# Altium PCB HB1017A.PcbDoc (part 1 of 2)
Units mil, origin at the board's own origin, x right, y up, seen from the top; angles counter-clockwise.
Board outline 2906.96 x 3469.35 mil, 2 copper layers (Top Layer, Bottom Layer); 52 components, 64 nets, 277 pads, 519 vias.
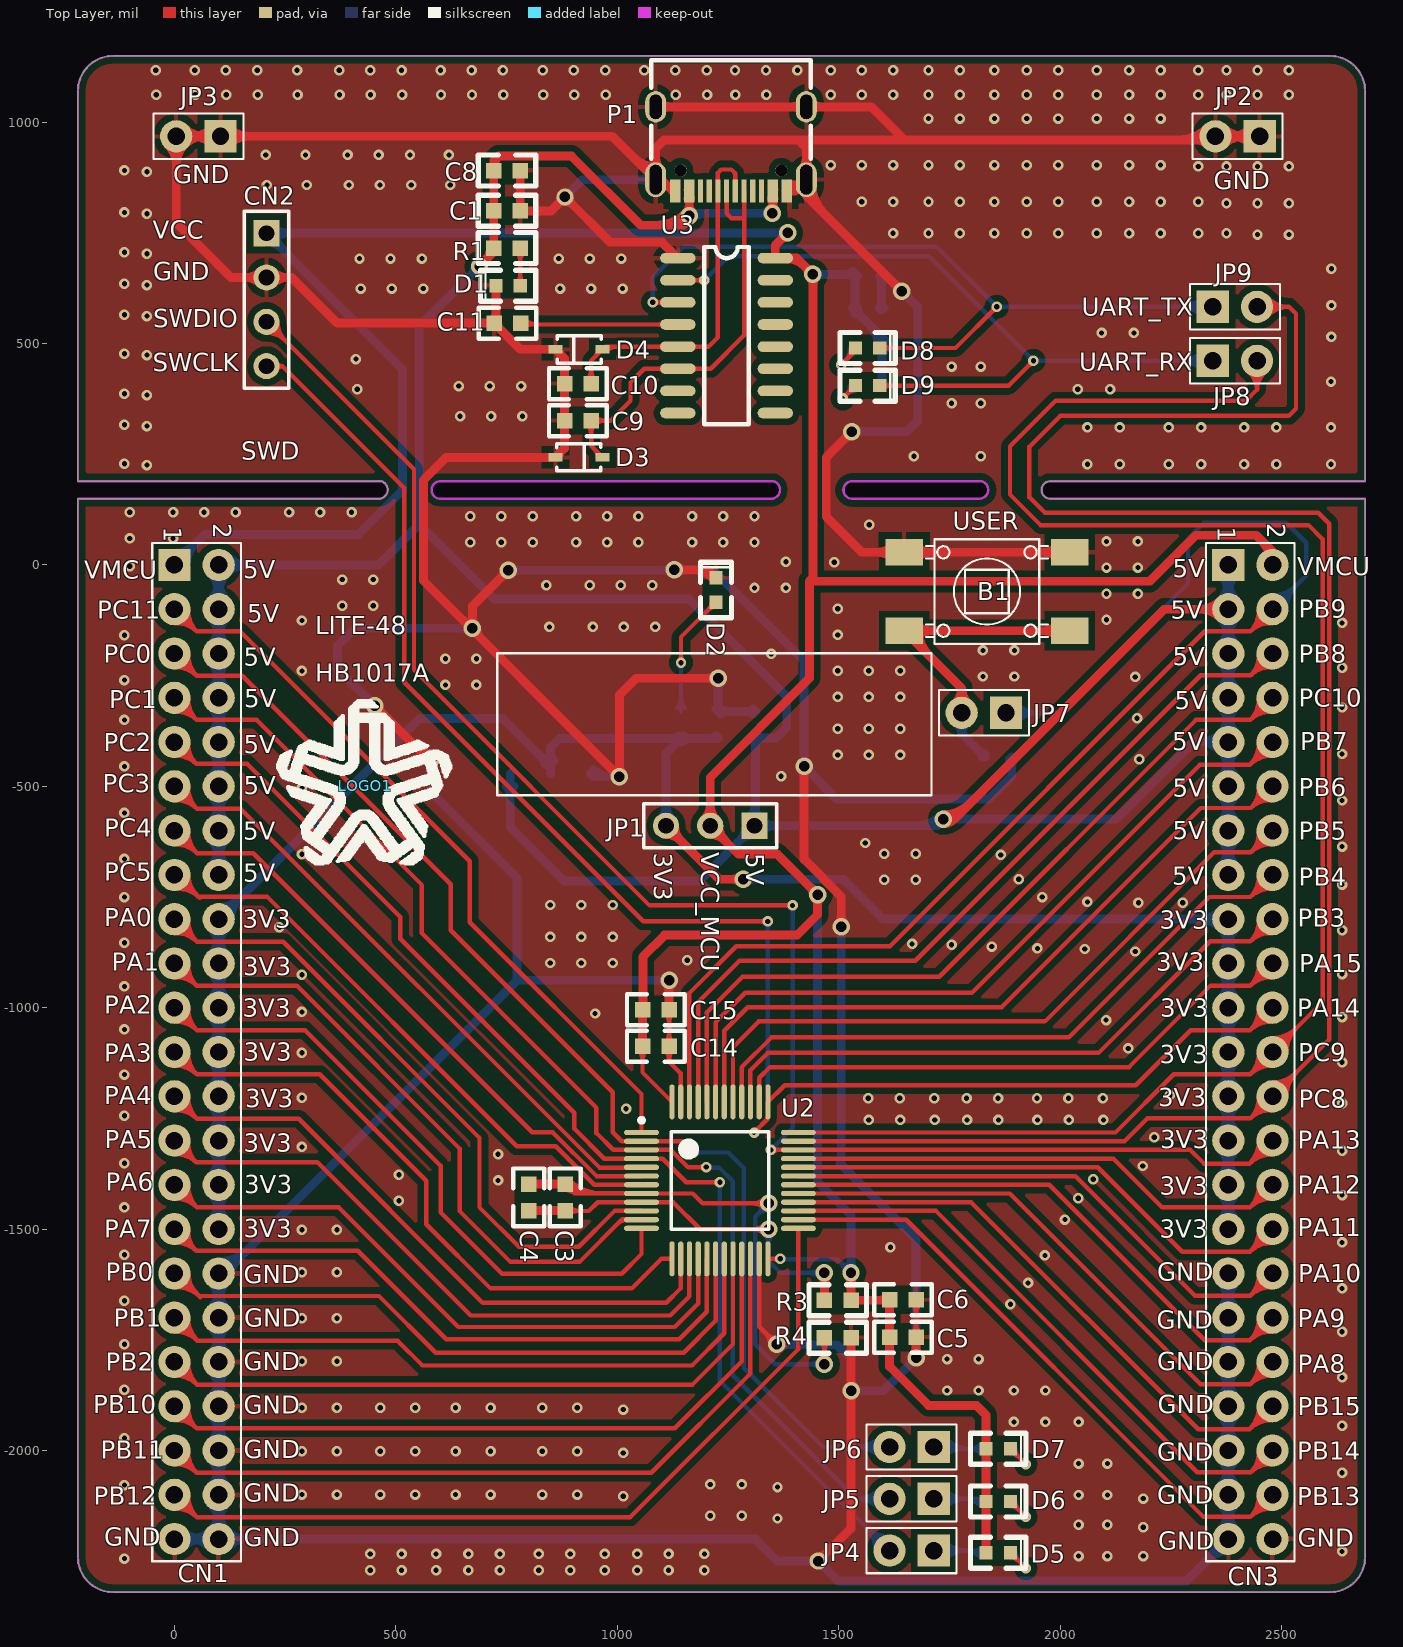
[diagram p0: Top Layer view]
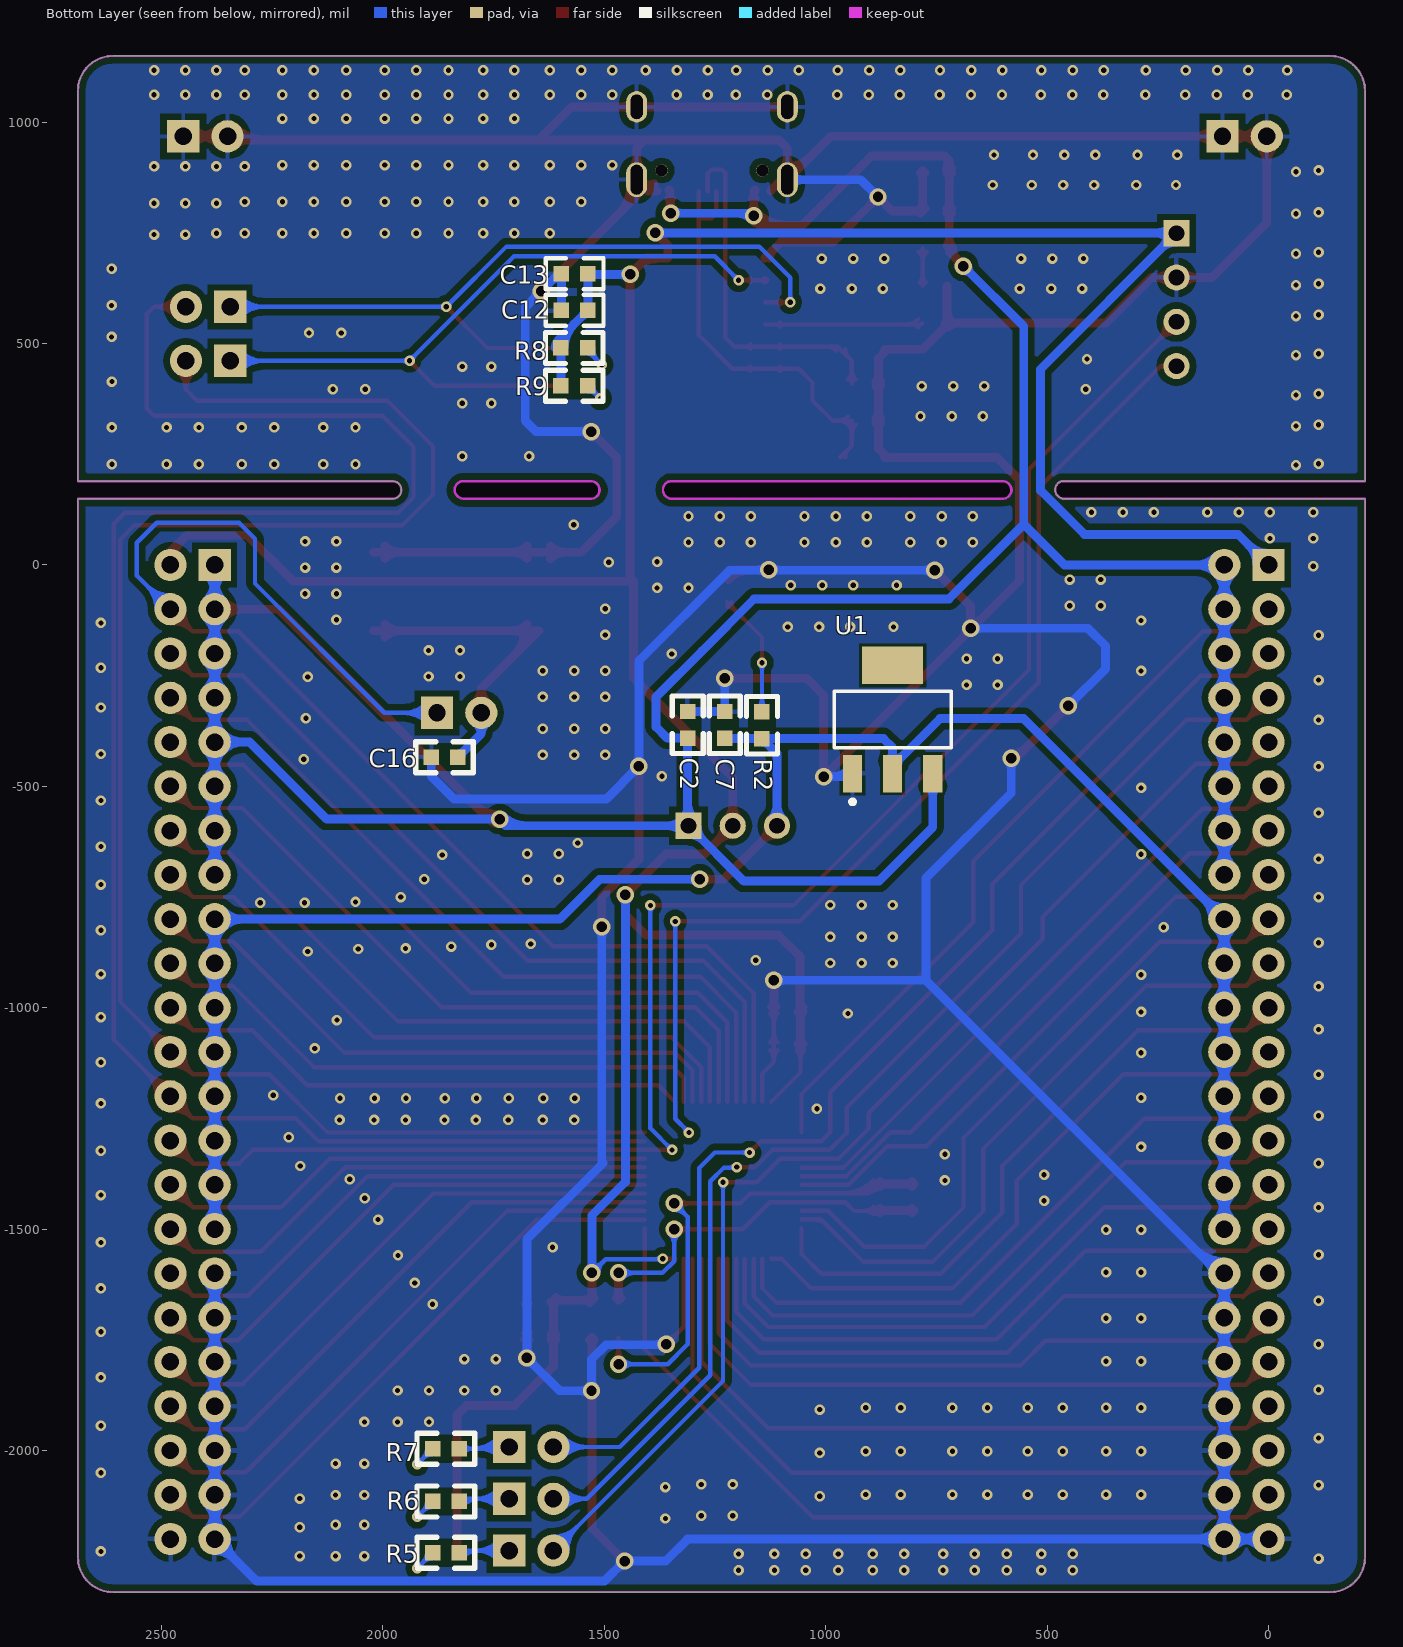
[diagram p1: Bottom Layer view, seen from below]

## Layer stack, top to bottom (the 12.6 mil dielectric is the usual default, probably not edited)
Top Layer: signal copper 1.4
Dielectric: dielectric 12.6, FR-4, Dk 4.8
Bottom Layer: signal copper 1.4

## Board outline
-217.95,-2241.01 ccw(c-139.21,-2241.01) -139.21,-2319.75 2610.22,-2319.75 ccw(c2610.22,-2241.01) 2688.96,-2241.01 2688.96,149.61 1978.04,149.61 cw(c1978.04,169.29) 1978.04,188.98 1978.04,189 2688.96,188.98 2688.96,1070.81 ccw(c2610.22,1070.81) 2610.22,1149.55 2529.22,1149.55 2529.22,1149.61 -139.21,1149.55 ccw(c-139.21,1070.81) -217.95,1070.81 -218,1070.87 -218,188.98 468,189 cw(c461.39,169.85) 464.74,149.86 464.39,149.61 -218,149.61
cut-out: 598.97,149.63 1347,149.63 ccw(c1347,169.31) 1347,189 598.97,189 ccw(c598.97,169.31)
cut-out: 1530,150.67 1818.59,150.67 ccw(c1818.59,170.35) 1818.59,190.04 1530,190.04 ccw(c1530,170.35)

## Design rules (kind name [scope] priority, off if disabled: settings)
Clearance [(IsPad and InComponent('U1'))] p1: gap=7
Clearance Clearance_poly [(InPolygon)] p2: gap=15
Clearance Clearance_CN [(IsPad and InComponent('CN1','CN4','U2'))] p3: gap=6
Clearance Clearance_Pad [All] p4: gap=5
ComponentClearance [All] p1: gap=0 collisioncheckmode=3 verticalgap=0 showdistances=FALSE
HoleSize [All] p1: absolutevalues=TRUE maxlimit=130 minlimit=1 maxpercent=80.000 minpercent=20.000
MinimumSolderMaskSliver [All] p1: minsoldermaskwidth=0
PolygonConnect PolygonConnect_Pads [IsPad] p1: connectstyle=Relief reliefconductorwidth=10 reliefentries=4 polygonreliefangle="90 Angle"
PolygonConnect [All] p2: connectstyle=Direct reliefconductorwidth=10 reliefentries=4 polygonreliefangle="90 Angle"
RoutingVias [All] p1: holewidth=12 width=20 viastyle="Through Hole" minholewidth=10 minwidth=18 maxholewidth=300 maxwidth=500
SilkToSilkClearance [All] p1: silktosilkclearance=0
SilkscreenOverComponentPads [IsPad] p1: minsilkscreentomaskgap=0
SolderMaskExpansion [All] p1: expansion=4
TestPointUsage [All] p1: valid=0 allowmultiple=FALSE
Testpoint [All] p1: side=3 testpointundercomponent=TRUE minsize=40 maxsize=100 preferedsize=60 minholesize=0 maxholesize=40 preferedholesize=32 testpointgrid=1 style=297 order=0123456789
Width [All] p1: maxlimit=20 minlimit=8 preferedwidth=10
19 further rules are at their usual default settings.

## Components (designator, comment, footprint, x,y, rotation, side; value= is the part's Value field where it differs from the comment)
B1 "SW-PUSH-CMS_BLACK" SWI_WEALTHMETAL_TD-0341_4P_BLACK 1835,-60 r270 top
C1 "10u" 0603 781.1,799.66 r180 top
C2 "10u" 0603 1312,-331 r270 bottom
C3 "1u" 0603C 883,-1428 r90 top
C4 "0.1u" 0603C 800.34,-1428 r90 top
C5 "1u" 0603C 1645.1,-1744.34 r0 top
C6 "0.1u" 0603C 1645.1,-1659.9 r0 top
C7 "10u" 0603 1228,-331 r270 bottom
C8 "0.1u" 0603 781.1,890.66 r180 top
C9 "DNP/100pF/50V" 0603C 911.05,325.66 r0 top
C10 "DNP/100pF/50V" 0603C 910.86,409.66 r180 top
C11 "0.1uF/25V" 0603C 752.19,545.66 r0 top
C12 "10uF/10V" 0603C 1566.9,574.72 r180 bottom
C13 "0.1uF/10V" 0603C 1566.9,657.06 r180 bottom
C14 "0.1u" 0603C 1087,-1087 r180 top
C15 "1u" 0603C 1087,-1004 r180 top
C16 "0.1u" 0603 1831,-434 r0 bottom
CN1 "Header 23x2" HEADER_1X23_2.54 0,0 r270 top locked
CN2 "Header 1X5" HDR1X4_2.54 208,749 r270 top
CN3 "Header 23x2" HEADER_1X23_2.54 2380,0 r270 top locked
D1 "LED_R" 0603-P 781.1,630.66 r180 top
D2 "LED_R" 0603-P 1223,-84 r90 top
D3 "DNP/PESD3V3L1BA" SOD323 860.7,243 r0 top
D4 "DNP/PESD3V3L1BA" SOD323 967,487 r180 top
D5 "LED_B" 0603-P 1832.98,-2231.04 r0 top
D6 "LED_R" 0603-P 1832.98,-2115 r0 top
D7 "LED_P" 0603-P 1832.98,-1995.99 r0 top
D8 "LED_B" 0603-P 1538,490 r0 top
D9 "LED_B" 0603-P 1538,405 r0 top
JP1 "Jumper_Header 3x1 Fitted" HDR1X3 1310,-589 r180 top locked
JP2 "Shunt Fitted" HEADER_1X2_2.54 2401,968 r180 top
JP3 "Shunt Fitted" HEADER_1X2_2.54 54,968 r180 top
JP4 "Shunt Fitted" HEADER_1X2_2.54 1665,-2226 r180 top
JP5 "Shunt Fitted" HEADER_1X2_2.54 1665,-2109 r180 top
JP6 "Shunt Fitted" HEADER_1X2_2.54 1665,-1992 r180 top
JP7 "Shunt Fitted" HEADER_1X2_2.54 1828,-334 r180 top
JP8 "Shunt Fitted" HEADER_1X2_2.54 2395,461 r0 top
JP9 "Shunt Fitted" HEADER_1X2_2.54 2395,583 r0 top
LOGO1 "LOGO" LOGO_HED_10mm 430.62,-498.7 r0 top
P1 "TYPE-C-16P" HED-KH-TYPE-C-16P 1427,870 r0 top locked
R1 "1K" 0603 721.1,715.66 r0 top
R2 "1K" 0603 1144,-332 r270 bottom
R3 "0R" 0603 1468,-1660.57 r0 top
R4 "0R" 0603 1468,-1745 r0 top
R5 "510R" 0603 1827.98,-2231.04 r0 bottom
R6 "510R" 0603 1887.98,-2115 r180 bottom
R7 "510R" 0603 1887.98,-1995.99 r180 bottom
R8 "DNP" 0603 1598,490 r180 bottom
R9 "DNP" 0603 1598,405 r180 bottom
U1 "AMS1117-3V3" SOT223 849,-349 r180 bottom locked
U2 "CIU32M030K5PBxJ" LQFP_48N_7X7 1232,-1390 r0 top locked
U3 "CH340C  SOP-16_150mil" SO-16 1137,693 r0 top locked

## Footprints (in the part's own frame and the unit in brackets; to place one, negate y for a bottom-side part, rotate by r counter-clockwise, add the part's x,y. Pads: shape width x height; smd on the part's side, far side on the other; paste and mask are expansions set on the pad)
0603 [mil]
  rect 35x35 smd: 1(0,0) 2(60,0)
  silkscreen extent -35,-35 95,35
0603-P [mil]
  rect 30x30 smd: 1(0,0) 2(55,0)
  silkscreen extent -35,-35 90,35, body extent 1,-15 60,15, height 10
0603C [mil]
  rect 35x35 smd: 1(-30.1,0.34) 2(29.9,0.34)
  silkscreen extent -65,-35 65,35, body extent -30,-16 30,16, height 10
HDR1X3 [mm] "Connector; Header; 3 Position"
  rect 1.5x1.5 hole 0.9: 1(0,0)
  round 1.5 hole 0.9: 2(2.54,0) 3(5.08,0)
  silkscreen extent -1.27,-1.27 6.35,1.27
HDR1X4_2.54 [mm]
  rect 1.5x1.5 hole 0.9: 1(0,0)
  round 1.5 hole 0.9: 2(2.54,0) 3(5.08,0) 4(7.62,0)
  silkscreen extent -1.27,-1.27 8.89,1.27
HEADER_1X2_2.54 [mm]
  rect 1.85x1.85 / inner round 1.85 / far side rect 1.85x1.85 hole 1: 1(-1.27,0)
  round 1.85 hole 1: 2(1.27,0)
  silkscreen extent -2.58,-1.3 2.58,1.3, body extent -2.67,-1.3 2.58,1.3, height 8.38
HEADER_1X23_2.54 [mm]
  rect 1.85x1.85 / inner round 1.85 / far side rect 1.85x1.85 hole 1: 1(0,0)
  round 1.85 hole 1: 2(0,2.54) 3(2.54,0) 4(2.54,2.54) 5(5.08,0) 6(5.08,2.54) 7(7.62,0) 8(7.62,2.54) 9(10.16,0) 10(10.16,2.54) 11(12.7,0) 12(12.7,2.54) 13(15.24,0) 14(15.24,2.54) 15(17.78,0) 16(17.78,2.54) 17(20.32,0) 18(20.32,2.54) 19(22.86,0) 20(22.86,2.54) 21(25.4,0) 22(25.4,2.54) 23(27.94,0) 24(27.94,2.54) 25(30.48,0) 26(30.48,2.54) 27(33.02,0) 28(33.02,2.54) 29(35.56,0) 30(35.56,2.54) 31(38.1,0) 32(38.1,2.54) 33(40.64,0) 34(40.64,2.54) 35(43.18,0) 36(43.18,2.54) 37(45.72,0) 38(45.72,2.54) 39(48.26,0) 40(48.26,2.54) 41(50.8,0) 42(50.8,2.54) 43(53.34,0) 44(53.34,2.54) 45(55.88,0) 46(55.88,2.54)
  silkscreen extent -1.27,-1.27 57.15,3.81, body extent -1.27,-1.4 57.15,3.81, height 8.38
HED-KH-TYPE-C-16P [mm]
  oval 1.2x2 hole 0.7 slot 1.7 at 90 deg: 1(0,0) 2(-8.64,0)
  oval 1.2x1.8 hole 0.7 slot 1.4 at 90 deg: 3(0,4.18) 4(-8.64,4.18)
  rect 0.3x1.3 smd: A1(-0.97,-0.65) A4(-1.77,-0.65) A5(-3.07,-0.65) A6(-4.07,-0.65) A7(-4.57,-0.65) A8(-5.57,-0.65) A9(-6.87,-0.65) A12(-7.67,-0.65) B1(-7.37,-0.65) B4(-6.57,-0.65) B5(-6.07,-0.65) B6(-5.07,-0.65) B7(-3.57,-0.65) B8(-2.57,-0.65) B9(-2.07,-0.65) B12(-1.27,-0.65)
  round 0.7 hole 0.7 unplated: ""(-7.21,0.53) ""(-1.43,0.53)
  silkscreen extent -8.89,1.19 0.25,6.84
LOGO_HED_10mm [mil]
  silkscreen extent -197,-176 193,192
LQFP_48N_7X7 [mm]
  oval 2x0.3 smd: 1(-4.5,2.75) 2(-4.5,2.25) 3(-4.5,1.75) 4(-4.5,1.25) 5(-4.5,0.75) 6(-4.5,0.25) 7(-4.5,-0.25) 8(-4.5,-0.75) 9(-4.5,-1.25) 10(-4.5,-1.75) 11(-4.5,-2.25) 12(-4.5,-2.75) 25(4.5,-2.75) 26(4.5,-2.25) 27(4.5,-1.75) 28(4.5,-1.25) 29(4.5,-0.75) 30(4.5,-0.25) 31(4.5,0.25) 32(4.5,0.75) 33(4.5,1.25) 34(4.5,1.75) 35(4.5,2.25) 36(4.5,2.75)
  oval 0.3x2 smd: 13(-2.75,-4.5) 14(-2.25,-4.5) 15(-1.75,-4.5) 16(-1.25,-4.5) 17(-0.75,-4.5) 18(-0.25,-4.5) 19(0.25,-4.5) 20(0.75,-4.5) 21(1.25,-4.5) 22(1.75,-4.5) 23(2.25,-4.5) 24(2.75,-4.5) 37(2.75,4.5) 38(2.25,4.5) 39(1.75,4.5) 40(1.25,4.5) 41(0.75,4.5) 42(0.25,4.5) 43(-0.25,4.5) 44(-0.75,4.5) 45(-1.25,4.5) 46(-1.75,4.5) 47(-2.25,4.5) 48(-2.75,4.5)
  silkscreen extent -4.62,-2.8 2.8,3.57, body extent -3.5,-3.5 3.5,3.5, height 1.6
SO-16 [mil]
  oval 80x24 smd: 1(0,0) 2(0,-50) 3(0,-100) 4(0,-150) 5(0,-200) 6(0,-250) 7(0,-300) 8(0,-350) 9(220,-350) 10(220,-300) 11(220,-250) 12(220,-200) 13(220,-150) 14(220,-100) 15(220,-50) 16(220,0)
  silkscreen extent 60,-375 160,25
SOD323 [mm]
  rect 0.8x0.5 smd: 1(0,0) 2(2.7,0)
  silkscreen extent 0.07,-0.77 2.59,0.79
SOT223 [mm]
  rect 1.1x2.15 smd: 1(-2.3,-3.1) 2(0,-3.1) 3(2.3,-3.1)
  rect 3.5x2.15 smd: 4(0,3.1)
  silkscreen extent -3.35,-4.85 3.35,1.63
SWI_WEALTHMETAL_TD-0341_4P_BLACK [mm]
  rect 1.52x2.16 smd: 1(-2.25,-4.75) 2(-2.25,4.75) 3(2.25,-4.75) 4(2.25,4.75)
  silkscreen extent -3,-3.5 3,3.5, body extent -3,-5.15 3,5.15, height 7.55

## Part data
B1: library part MCD-00001, "Non-Open Push-Button 0.1A 24V"
C1: library part "0603 4.7uF 10% 16V", "贴片电容"
C2 C7: library part MCD-00014, "贴片电容"
C3 C5 C15: library part CAP, "105贴片电容"
C4: library part CAP, "104/25V贴片电容"
C6 C14: library part CAP, "104贴片电容"
C8: library part "0603 100nF 10% 50V", "贴片电容"
C9 C10 C11 C12 C13: library part "cap 0603", "贴片电容"
C16: library part MCD-00211, "Capacitor, MLCC, 100nF, 16V, X7R, 10%, 0603, T=0,8mm"
CN1: "Header, 19x2, 2,54mm, VR, TH, Height 5.84mm/10.16mm"
CN2: library part CON4, "排针Header 1X5，2.54mm"
CN3: "长排针Header 23x2，2.54mm"
D1: library part LED3, "Typical BLUE SiC LED"
D2 D5 D6 D7 D8 D9: library part LED1, "Typical RED GaAs LED"
D3 D4: library part TVS
JP1: "Jumper_Header 1X3 2.54mm"
JP2: library part "Jumper_Header 2x1 Fitted", "Header, 2x1, 2,54mm,"
JP3: library part "Jumper_Header 2x1 Fitted", "Header, 2x1, 2,54mm"
JP4 JP5 JP6 JP8: library part MCD-00683, "Header, 2x1, 2,54mm,"
JP7: library part MCD-00683, "Header, 2x1, 2,54mm, VR, TH, Height 5.84mm/2.54mm - Shunt Fitted by default"
JP9: library part MCD-00683, "Header, 2x1, 2,54mm"
P1: library part KH-TYPE-C-16P, "TYPE-C USB接口"
R1 R2 R5 R6 R7: library part Res2, "贴片电阻"
R3 R4: library part Res, "贴片电阻"
R8 R9: library part "res 0603", "贴片电阻"
U1: library part AMS1117, "IC REG LDO 5V 0.8A SOT223"
U2: "LQFP48"
U3: library part CH340C, "IC"

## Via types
v1: diameter 23.62, hole 11.81, Top Layer to Bottom Layer, tented both sides, 489 vias
v2: diameter 39.37, hole 23.62, Top Layer to Bottom Layer, tented both sides, 30 vias

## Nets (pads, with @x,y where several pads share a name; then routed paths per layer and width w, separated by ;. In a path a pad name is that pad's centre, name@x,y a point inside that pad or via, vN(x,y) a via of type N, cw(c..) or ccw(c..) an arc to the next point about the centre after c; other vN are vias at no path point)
AVCC_MCU: C3.1 C4.1 R3.1 U2.9 | length 1183
  Top Layer w10: C3.1@882.66,-1458.1 883.57,-1459 936,-1459 955.79,-1439.21 U2.9@1054.83,-1439.21 1126.21,-1439.21 1187.24,-1500.24 v2(1342.24,-1500.24) ; C3.1@891.5,-1466.93 cw(c910.66,-1486.09) 910.66,-1459 ; C3.1@891.5,-1449.26 ccw(c915.02,-1425.73) 915.02,-1459 ; v2@1331.85,-1510.62 ccw(c1306.78,-1535.69) 1306.78,-1500.24 ccw(c1306.78,-1464.78) v2@1331.85,-1489.85
  Top Layer w20: C4.1@800,-1458.1 C3.1@882.66,-1458.1 ; C4.1@805.3,-1463.4 cw(c818.11,-1476.2) 818.11,-1458.1 cw(c818.11,-1439.99) C4.1@805.3,-1452.79 ; C3.1@877.36,-1463.4 ccw(c864.56,-1476.2) 864.56,-1458.1 ccw(c864.56,-1439.99) C3.1@877.36,-1452.79 ; v2@1461.15,-1605.85 cw(c1444.62,-1622.38) 1468,-1622.38 cw(c1491.38,-1622.38) v2@1474.85,-1605.85 ; R3.1@1462.7,-1655.26 ccw(c1449.89,-1642.46) 1468,-1642.46 ccw(c1486.11,-1642.46) R3.1@1473.3,-1655.26 ; R3.1@1468,-1660.57 v2(1468,-1599)
  Bottom Layer w10: v2@1331.85,-1510.62 cw(c1306.78,-1535.69) 1342.24,-1535.69 cw(c1377.69,-1535.69) v2@1352.62,-1510.62 ; v2(1342.24,-1500.24) 1342.24,-1572.25 1368.99,-1599 v2(1468,-1599) ; v2@1457.62,-1609.38 ccw(c1432.55,-1634.45) 1432.55,-1599 ccw(c1432.55,-1563.55) v2@1457.62,-1588.62
AVSS: C3.2 C4.2 R4.1 U2.8 | length 1681
  Top Layer w10: C3.2@877.36,-1403.4 ccw(c915.02,-1365.73) 915.02,-1419 ; C3.2@882.66,-1398.1 903.57,-1419 ; C3.2@882.85,-1410.59 cw(c883.27,-1439.3) 903.57,-1419 ; C3.2@884.43,-1396.33 ccw(c939.17,-1341.59) 939.17,-1419 ; C3.2@891.5,-1389.26 ccw(c963.31,-1317.45) 963.31,-1419 ; C3.2@895.16,-1398.28 ccw(c923.86,-1398.7) 903.57,-1419 ; v2@1331.85,-1452.38 ccw(c1306.78,-1477.45) 1306.78,-1442 ccw(c1306.78,-1406.55) v2@1331.85,-1431.62 ; v2(1342.24,-1442) 1193,-1442 1170.53,-1419.53 U2.8@1054.83,-1419.53 1054.31,-1419 903.57,-1419 ; v2@1457.62,-1794.62 ccw(c1432.55,-1769.55) 1468,-1769.55 ccw(c1503.45,-1769.55) v2@1478.38,-1794.62 ; R4.1@1459.16,-1753.84 cw(c1437.82,-1775.18) 1468,-1775.18 cw(c1498.18,-1775.18) R4.1@1476.84,-1753.84 ; v2(1468,-1805) R4.1@1468,-1745
  Top Layer w20: C4.2@800,-1398.1 C3.2@882.66,-1398.1 ; C4.2@805.3,-1403.4 cw(c818.11,-1416.2) 818.11,-1398.1 cw(c818.11,-1379.99) C4.2@805.3,-1392.79 ; C3.2@877.36,-1403.4 ccw(c864.56,-1416.2) 864.56,-1398.1 ccw(c864.56,-1379.99) C3.2@877.36,-1392.79
  Bottom Layer w10: v2@1327.55,-1442 cw(c1292.1,-1442) 1317.17,-1467.07 cw(c1342.24,-1492.14) v2@1342.24,-1456.69 ; v2(1342.24,-1442) 1312,-1472.24 1312,-1760 1357,-1805 v2(1468,-1805) ; v2@1457.62,-1815.38 ccw(c1432.55,-1840.45) 1432.55,-1805 ccw(c1432.55,-1769.55) v2@1457.62,-1794.62
GND: B1.1 B1.2 C1.1 C2.1 C5.2 C6.2 C7.1 C8.1 C9.1 C10.2 C11.1 C12.1 C13.1 C14.1 C15.1 C16.2 CN1.34 CN1.36 CN1.38 CN1.40 CN1.42 CN1.44 CN1.45 CN1.46 CN2.2 CN3.33 CN3.35 CN3.37 CN3.39 CN3.41 CN3.43 CN3.45 CN3.46 D1.2 D2.2 D3.1 D4.2 JP2.1 JP2.2 JP3.1 JP3.2 P1.1 P1.2 P1.3 P1.4 P1.A1 P1.A12 P1.B1 P1.B12 R4.2 U1.1 U2.23 U2.47 U3.1 | length 27442.4
  Top Layer w10: C14.1@1108.26,-1096.18 cw(c1086.92,-1117.52) 1117.1,-1117.52 cw(c1147.27,-1117.52) C14.1@1125.93,-1096.18 ; C14.1@1108.26,-1078.5 ccw(c1086.92,-1057.16) 1117.1,-1057.16 ccw(c1147.27,-1057.16) C14.1@1125.93,-1078.5 ; C15.1@1108.26,-1013.18 cw(c1086.92,-1034.52) 1117.1,-1034.52 cw(c1147.27,-1034.52) C15.1@1125.93,-1013.18 ; C15.1@1117.1,-1004.34 C14.1@1117.1,-1087.34 1117.1,-1122.1 1143.42,-1148.42 U2.47@1143.42,-1212.83 ; U2.23@1320.58,-1567.17 1320.58,-1720.58 v2(1360,-1760) ; v2@1345.31,-1760 ccw(c1309.86,-1760) 1334.93,-1734.93 ccw(c1360,-1709.86) v2@1360,-1745.31 ; C5.2@1666.16,-1735.16 ccw(c1644.82,-1713.82) 1675,-1713.82 ccw(c1705.18,-1713.82) C5.2@1683.84,-1735.16 ; C6.2@1666.16,-1668.4 cw(c1644.82,-1689.74) 1675,-1689.74 cw(c1705.18,-1689.74) C6.2@1683.84,-1668.4 ; C5.2@1675,-1744 C6.2@1675,-1659.57
  Top Layer w20: JP3.2@-14.68,949.32 cw(c-59.78,904.22) 4,904.22 cw(c67.78,904.22) 22.68,949.32 cw(c67.78,904.22) 67.78,968 cw(c67.78,1031.78) JP3.2@22.68,986.68 ; JP3.1@85.32,949.32 ccw(c40.22,904.22) 40.22,968 ccw(c40.22,1031.78) JP3.1@85.32,986.68 ; JP3.1@122.68,949.32 cw(c167.78,904.22) 167.78,968 cw(c167.78,1031.78) JP3.1@122.68,986.68 ; CN2.2@194.19,635.19 ccw(c160.86,601.86) 160.86,649 ccw(c160.86,696.14) CN2.2@194.19,662.81 ; CN2.2@221.81,635.19 cw(c255.14,601.86) 255.14,649 cw(c255.14,696.14) CN2.2@221.81,662.81 ; v2@452,-327.68 cw(c452,-351.07) 468.53,-334.53 cw(c485.07,-318) v2@461.69,-318 ; v2(452,-318) 571,-437 v2(581,-437) ; 547.4,-413.4 ccw(c581,-379.79) v2@581,-427.32 ; 651.35,-124.35 ccw(c673,-102.69) v2@673,-133.32 ; v2@666.15,-136.15 ccw(c649.62,-119.62) 673,-119.62 ccw(c696.38,-119.62) v2@679.85,-136.15 ; v2(673,-143) 673,-93 v2(754,-12) ; v2@682.68,-143 ccw(c713.31,-143) 691.65,-164.65 ; C11.1@716.79,540.7 ccw(c703.99,527.89) 703.99,546 ccw(c703.99,564.11) 716.79,551.3 ccw(c694.33,573.76) 726.1,573.76 ; C11.1@722.1,538.5 cw(c722.1,520.39) 734.9,533.2 cw(c747.7,546) C11.1@729.6,546 ; D1.2@726.1,630.66 726.1,550 C11.1@722.1,546 ; v2@744.31,-12 cw(c720.93,-12) 737.47,-28.53 cw(c754,-45.07) v2@754,-21.69 ; C1.1@775.79,804.97 ccw(c762.99,817.77) 781.1,817.77 ccw(c799.2,817.77) 786.4,804.97 ccw(c799.2,817.77) 799.2,799.66 ccw(c799.2,781.56) C1.1@786.4,794.36 ; C8.1@775.79,885.36 cw(c762.99,872.56) 781.1,872.56 cw(c799.2,872.56) C8.1@786.4,885.36 ; C8.1@781.1,890.66 C1.1@781.1,799.66 850.66,799.66 v2(882,831) 984,729 1101,729 U3.1@1137,693 ; D3.1@866.45,243 cw(c880.33,243) D3.1@870.51,252.81 ; D4.2@866.45,487 ccw(c880.33,487) D4.2@870.51,477.19 ; v2@872.31,831 cw(c848.93,831) 865.47,814.47 cw(c882,797.93) 882,821.31 cw(c882,797.93) 898.53,814.47 cw(c915.07,831) v2@891.69,831 ; C9.1@875.65,320.7 cw(c862.85,307.89) 880.95,307.89 cw(c899.06,307.89) C9.1@886.26,320.7 ; C9.1@875.65,331.3 ccw(c862.85,344.11) 880.95,344.11 ccw(c899.06,344.11) C9.1@886.26,331.3 ; C10.2@875.65,404.02 cw(c862.85,391.22) 880.95,391.22 cw(c899.06,391.22) C10.2@886.26,404.02 ; C10.2@875.65,414.63 ccw(c862.85,427.43) 880.95,427.43 ccw(c899.06,427.43) C10.2@886.26,414.63 ; v2@995.31,-478 ccw(c971.93,-478) 988.47,-461.47 ccw(c1005,-444.93) v2@1005,-468.32 ; v2@998.15,-471.15 ccw(c981.62,-454.62) 1005,-454.62 ccw(c1028.38,-454.62) v2@1011.85,-471.15 ; 1036.71,920.14 ccw(c1086.84,970.28) P1.2@1086.84,899.37 ; P1.2@1077.21,895.38 ccw(c1053.96,918.63) 1086.84,918.63 ccw(c1119.73,918.63) P1.2@1096.48,895.38 ; P1.2@1078.31,879.21 cw(c1083.18,864.97) P1.2@1093.82,875.61 ; P1.2@1084.78,860.29 cw(c1094.74,831.15) 1116.51,852.92 ; P1.4@1086.84,1034.57 P1.3@1427,1034.57 1573.43,1034.57 1648,960 ; P1.4@1096.48,1024.93 cw(c1119.73,1001.68) 1119.73,1034.57 cw(c1119.73,1067.45) P1.4@1096.48,1044.2 ; v2@1110.25,-944.85 cw(c1093.71,-961.38) 1117.1,-961.38 cw(c1140.48,-961.38) v2@1123.94,-944.85 ; C15.1@1111.79,-999.03 ccw(c1098.99,-986.23) 1117.1,-986.23 ccw(c1135.2,-986.23) C15.1@1122.4,-999.03 ; C15.1@1117.1,-1004.34 v2(1117.1,-938) ; 1120.03,709.97 cw(c1103.2,693.14) U3.1@1126.99,692.57 ; P1.A12@1125.03,844.4 1099.43,870 P1.2@1086.84,870 ; v2(1129,-11) 1205,-11 D2.2@1223,-29 ; v2@1135.85,-17.85 cw(c1152.38,-34.38) 1152.38,-11 cw(c1152.38,12.38) v2@1135.85,-4.15 ; 1167.47,-11 cw(c1167.47,-84.53) D2.2@1219.46,-32.54 ; v2@1221.15,-262.85 ccw(c1204.62,-279.38) 1204.62,-256 ccw(c1204.62,-232.62) v2@1221.15,-249.15 ; v2(1228,-256) 1043,-256 1005,-294 1005,-417 v2(1005,-478) 562.17,-35.17 562.17,191.17 614,243 D3.1@860.7,243 880.95,263.25 C9.1@880.95,326 C10.2@880.95,409.32 880.95,466.75 D4.2@860.7,487 781.1,487 C11.1@722.1,546 ; P1.B12@1381.48,844.4 P1.A1@1388.81,844.4 ; P1.A1@1387.62,860.17 ccw(c1399.12,897.87) P1.1@1427,870 ; P1.1@1414.85,860.4 cw(c1388.81,873.58) P1.A1@1388.81,844.4 ; v2@1415.15,-461.85 cw(c1398.62,-478.38) 1422,-478.38 cw(c1445.38,-478.38) v2@1428.85,-461.85 ; P1.1@1417.37,895.38 ccw(c1394.11,918.63) 1427,918.63 ccw(c1459.89,918.63) P1.1@1436.63,895.38 ; P1.3@1417.37,1024.93 ccw(c1394.11,1001.68) 1394.11,1034.57 ccw(c1394.11,1067.45) P1.3@1417.37,1044.2 ; P1.1@1420.62,854.25 ccw(c1454.12,854.25) 1430.43,830.57 ; v2(1422,-455) 1422,-664.95 1506,-748.95 v2(1506,-817) ; P1.3@1436.63,1024.93 cw(c1459.89,1001.68) 1459.89,1034.57 cw(c1459.89,1067.45) P1.3@1436.63,1044.2 ; P1.1@1440.62,854.25 ccw(c1522.4,854.25) 1464.57,796.43 ; v2(1454.42,-2249.58) 1528,-2176 R4.2@1528,-1745 ; v2@1454.42,-2239.9 ccw(c1454.42,-2216.52) 1470.95,-2233.05 ccw(c1487.48,-2249.58) v2@1464.1,-2249.58 ; v2@1499.15,-810.15 ccw(c1482.62,-793.62) 1506,-793.62 ccw(c1529.38,-793.62) v2@1512.85,-810.15 ; v2@1520.31,301 cw(c1496.93,301) 1513.47,284.47 cw(c1530,267.93) v2@1530,291.31 ; v2@1522.15,-1871.85 cw(c1508.03,-1885.97) 1528,-1885.97 ; v2@1522.15,-1858.15 ccw(c1508.03,-1844.03) 1528,-1844.03 ; R4.2@1522.7,-1750.3 cw(c1509.89,-1763.11) 1528,-1763.11 cw(c1546.11,-1763.11) R4.2@1533.3,-1750.3 ; 1528,-1890.8 cw(c1554.8,-1890.8) v2@1535.85,-1871.85 ; 1528,-1839.2 ccw(c1554.8,-1839.2) v2@1535.85,-1858.15 ; v2(1530,301) 1472,243 1472,109 1552.42,28.58 B1.1@1647.99,28.58 B1.2@2022.01,28.58 ; B1.1@1621.31,14.5 ccw(c1587.3,-19.51) 1587.3,28.58 ccw(c1587.3,76.68) B1.1@1621.31,42.67 ; v2@1633.31,618 ccw(c1609.93,618) 1626.47,634.53 ccw(c1643,651.07) v2@1643,627.69 ; v2(1643,618) 1427,834 P1.1@1427,870 ; v2@1668.15,-1784.15 ccw(c1651.62,-1767.62) 1675,-1767.62 ccw(c1698.38,-1767.62) v2@1681.85,-1784.15 ; C5.2@1669.7,-1749.3 cw(c1656.89,-1762.11) 1675,-1762.11 cw(c1693.11,-1762.11) C5.2@1680.3,-1749.3 ; B1.1@1674.68,14.5 cw(c1708.68,-19.51) 1708.68,28.58 cw(c1708.68,76.68) B1.1@1674.68,42.67 ; v2(1675,-1791) C5.2@1675,-1744 ; B1.2@1995.32,14.5 ccw(c1961.32,-19.51) 1961.32,28.58 ccw(c1961.32,76.68) B1.2@1995.32,42.67 ; 2267.91,960 ccw(c2267.91,1051.09) JP2.2@2332.32,986.68 ; 2306.54,960 cw(c2306.54,923.54) JP2.2@2332.32,949.32 ; JP2.2@2369.68,949.32 cw(c2414.78,904.22) 2414.78,968 cw(c2414.78,1031.78) JP2.2@2369.68,986.68 ; JP2.1@2432.32,949.32 ccw(c2387.22,904.22) 2387.22,968 ccw(c2387.22,1031.78) JP2.1@2432.32,986.68 ; JP2.1@2451,968 JP2.2@2351,968 2343,960 1648,960 ; C11.1@722.1,546 368,546 265,649 CN2.2@208,649 128,649 4,773 JP3.2@4,968 JP3.1@104,968 988.84,968 P1.2@1086.84,870 ; P1.2@1086.84,870 1086.84,940.84 1106,960 1409,960 ; P1.A1@1388.81,844.4 1401.4,844.4 P1.1@1427,870 ; 1409,960 1648,960 ; 1409,960 1427,942 P1.1@1427,870
  Bottom Layer w20: CN1.45@0,-2200 CN1.46@100,-2200 ; CN1.45@18.68,-2218.68 cw(c63.78,-2263.78) 63.78,-2200 cw(c63.78,-2136.22) CN1.45@18.68,-2181.32 ; CN1.46@81.32,-2218.68 ccw(c36.22,-2263.78) 36.22,-2200 ccw(c36.22,-2136.22) 81.32,-2181.32 ccw(c36.22,-2136.22) 100,-2136.22 ccw(c163.78,-2136.22) 118.68,-2181.32 ccw(c163.78,-2136.22) 163.78,-2200 ccw(c163.78,-2263.78) CN1.46@118.68,-2218.68 ; CN1.44@81.32,-2118.68 cw(c36.22,-2163.78) 100,-2163.78 cw(c163.78,-2163.78) CN1.44@118.68,-2118.68 ; CN1.44@81.32,-2081.32 ccw(c36.22,-2036.22) 100,-2036.22 ccw(c163.78,-2036.22) CN1.44@118.68,-2081.32 ; CN1.42@81.32,-2018.68 cw(c36.22,-2063.78) 100,-2063.78 cw(c163.78,-2063.78) CN1.42@118.68,-2018.68 ; CN1.42@81.32,-1981.32 ccw(c36.22,-1936.22) 100,-1936.22 ccw(c163.78,-1936.22) CN1.42@118.68,-1981.32 ; CN1.40@81.32,-1918.68 cw(c36.22,-1963.78) 100,-1963.78 cw(c163.78,-1963.78) CN1.40@118.68,-1918.68 ; CN1.40@81.32,-1881.32 ccw(c36.22,-1836.22) 100,-1836.22 ccw(c163.78,-1836.22) CN1.40@118.68,-1881.32 ; CN1.38@81.32,-1818.68 cw(c36.22,-1863.78) 100,-1863.78 cw(c163.78,-1863.78) CN1.38@118.68,-1818.68 ; CN1.38@81.32,-1781.32 ccw(c36.22,-1736.22) 100,-1736.22 ccw(c163.78,-1736.22) CN1.38@118.68,-1781.32 ; CN1.36@81.32,-1718.68 cw(c36.22,-1763.78) 100,-1763.78 cw(c163.78,-1763.78) CN1.36@118.68,-1718.68 ; CN1.36@81.32,-1681.32 ccw(c36.22,-1636.22) 100,-1636.22 ccw(c163.78,-1636.22) CN1.36@118.68,-1681.32 ; CN1.34@81.32,-1618.68 cw(c36.22,-1663.78) 100,-1663.78 cw(c163.78,-1663.78) CN1.34@118.68,-1618.68 ; CN1.34@100,-1593.58 ccw(c100,-1549.12) 131.44,-1580.56 ; CN1.34@100,-1573.58 ccw(c100,-1480.84) 165.58,-1546.42 ; CN1.34@126.42,-1600 cw(c161.22,-1600) 136.61,-1575.39 ; v2@442.31,-318 ccw(c418.93,-318) 435.47,-301.47 ccw(c452,-284.93) v2@452,-308.32 ; v2(452,-318) 368,-234 368,-183 408,-143 v2(673,-143) ; v2@574.15,-443.85 cw(c557.62,-460.38) 581,-460.38 cw(c604.38,-460.38) v2@587.85,-443.85 ; v2(581,-437) 581,-515 774,-708 774,-938 ; v2@666.15,-149.85 ccw(c649.62,-166.38) 649.62,-143 ccw(c649.62,-119.62) v2@666.15,-136.15 ; v2(754,-12) 1217,-12 1422,-217 v2@1422,-452 ; v2@760.85,-18.85 cw(c777.38,-35.38) 777.38,-12 cw(c777.38,11.38) v2@760.85,-5.15 ; v2(882,831) 921,870 P1.2@1086.84,870 ; v2@882,840.69 ccw(c882,864.07) 898.53,847.53 ccw(c915.07,831) v2@891.69,831 ; U1.1@939.55,-471.05 946.5,-478 v2(1005,-478) ; U1.1@947.79,-462.81 ccw(c984.47,-426.13) 984.47,-478 ; v2@998.15,-484.85 ccw(c981.62,-501.38) 981.62,-478 ccw(c981.62,-454.62) v2@998.15,-471.15 ; P1.2@1077.21,860.37 ccw(c1053.96,837.11) 1053.96,870 ccw(c1053.96,902.89) P1.2@1077.21,879.63 ; 1103.2,-12 ccw(c1103.2,14.8) v2@1122.15,-4.15 ; 1108.03,-12 cw(c1108.03,-31.97) v2@1122.15,-17.85 ; v2@1110.25,-944.85 ccw(c1093.71,-961.38) 1093.71,-938 ccw(c1093.71,-914.62) v2@1110.25,-931.15 ; v2(1117.1,-938) 774,-938 ; v2@1135.85,-17.85 cw(c1149.97,-31.97) 1149.97,-12 ; v2@1135.85,-4.15 ccw(c1154.8,14.8) 1154.8,-12 ; v2@1221.15,-262.85 cw(c1204.62,-279.38) 1228,-279.38 cw(c1251.38,-279.38) v2@1234.85,-262.85 ; C7.1@1222.7,-325.7 ccw(c1209.89,-312.89) 1228,-312.89 ccw(c1246.11,-312.89) 1233.3,-325.7 ccw(c1246.11,-312.89) 1246.11,-331 ccw(c1246.11,-349.11) C7.1@1233.3,-336.3 ; v2(1228,-256) C7.1@1228,-331 C2.1@1312,-331 ; C2.1@1306.7,-336.3 ccw(c1293.89,-349.11) 1293.89,-331 ccw(c1293.89,-312.89) C2.1@1306.7,-325.7 ; v2(1360,-1760) 1361,-1761 1496,-1761 1529,-1794 v2(1529,-1865) 1601,-1865 v2(1675,-1791) 1675,-1523 1503,-1351 1506,-1348 v2(1506,-817) ; v2@1366.85,-1766.85 cw(c1380.97,-1780.97) 1380.97,-1761 ; v2@1366.85,-1753.15 ccw(c1385.8,-1734.2) 1385.8,-1761 ; v2@1415.15,-448.15 ccw(c1398.62,-431.62) 1422,-431.62 ccw(c1445.38,-431.62) v2@1428.85,-448.15 ; v2@1419,-449 v2@1422,-452 ; v2@1422,-464.68 cw(c1422,-488.07) 1438.53,-471.53 cw(c1455.07,-455) v2@1431.69,-455 ; v2@1423.5,-453.5 v2@1422,-452 ; v2@1447.57,-2256.43 ccw(c1431.04,-2272.96) 1431.04,-2249.58 ccw(c1431.04,-2226.2) v2@1447.57,-2242.73 ; v2@1454.42,-2259.27 cw(c1454.42,-2282.65) 1470.95,-2266.12 cw(c1487.48,-2249.58) v2@1464.1,-2249.58 ; v2@1499.15,-823.85 cw(c1482.62,-840.38) 1506,-840.38 cw(c1529.38,-840.38) v2@1512.85,-823.85 ; v2@1522.15,-1858.15 ccw(c1505.62,-1841.62) 1529,-1841.62 ccw(c1552.38,-1841.62) 1535.85,-1858.15 ccw(c1552.38,-1841.62) 1552.38,-1865 ccw(c1552.38,-1888.38) v2@1535.85,-1871.85 ; v2(1530,301) 1654,301 1678.69,325.69 1678.69,582.31 v2(1643,618) 1603.61,657.39 C13.1@1597,657.39 C12.1@1597,575.06 ; v2@1536.85,294.15 cw(c1553.38,277.62) 1553.38,301 cw(c1553.38,324.38) v2@1536.85,307.85 ; C12.1@1591.7,580.36 ccw(c1578.89,593.16) 1597,593.16 ccw(c1615.11,593.16) C12.1@1602.3,580.36 ; C13.1@1591.7,652.09 cw(c1578.89,639.29) 1597,639.29 cw(c1615.11,639.29) C13.1@1602.3,652.09 ; C13.1@1597,649.89 cw(c1597,615.84) 1621.08,639.92 ; v2@1633.31,618 ccw(c1609.93,618) 1626.47,634.53 ccw(c1643,651.07) v2@1643,627.69 ; v2@1643,608.31 cw(c1643,584.93) 1659.53,601.47 cw(c1676.07,618) v2@1652.69,618 ; v2@1665.31,-1791 cw(c1641.93,-1791) 1658.47,-1807.53 cw(c1675,-1824.07) v2@1675,-1800.68 ; v2@1668.15,-1784.15 ccw(c1651.62,-1767.62) 1675,-1767.62 ccw(c1698.38,-1767.62) v2@1681.85,-1784.15 ; C16.2@1885.7,-439.3 cw(c1872.89,-452.11) 1891,-452.11 cw(c1909.11,-452.11) C16.2@1896.3,-439.3 ; C16.2@1891,-434 1891,-477 1839,-529 1496,-529 v2(1422,-455) v2@1422,-452 ; CN3.45@2353.58,-2200 cw(c2289.81,-2200) 2334.9,-2245.1 cw(c2380,-2290.19) CN3.45@2380,-2226.42 ; CN3.45@2361.32,-2181.32 ccw(c2316.22,-2136.22) 2380,-2136.22 ccw(c2443.78,-2136.22) CN3.45@2398.68,-2181.32 ; CN3.43@2361.32,-2118.68 cw(c2316.22,-2163.78) 2380,-2163.78 cw(c2443.78,-2163.78) CN3.43@2398.68,-2118.68 ; CN3.43@2361.32,-2081.32 ccw(c2316.22,-2036.22) 2380,-2036.22 ccw(c2443.78,-2036.22) CN3.43@2398.68,-2081.32 ; CN3.41@2361.32,-2018.68 cw(c2316.22,-2063.78) 2380,-2063.78 cw(c2443.78,-2063.78) CN3.41@2398.68,-2018.68 ; CN3.41@2361.32,-1981.32 ccw(c2316.22,-1936.22) 2380,-1936.22 ccw(c2443.78,-1936.22) CN3.41@2398.68,-1981.32 ; CN3.39@2361.32,-1918.68 cw(c2316.22,-1963.78) 2380,-1963.78 cw(c2443.78,-1963.78) CN3.39@2398.68,-1918.68 ; CN3.39@2361.32,-1881.32 ccw(c2316.22,-1836.22) 2380,-1836.22 ccw(c2443.78,-1836.22) CN3.39@2398.68,-1881.32 ; CN3.37@2361.32,-1818.68 cw(c2316.22,-1863.78) 2380,-1863.78 cw(c2443.78,-1863.78) CN3.37@2398.68,-1818.68 ; CN3.37@2361.32,-1781.32 ccw(c2316.22,-1736.22) 2380,-1736.22 ccw(c2443.78,-1736.22) CN3.37@2398.68,-1781.32 ; CN3.35@2361.32,-1718.68 cw(c2316.22,-1763.78) 2380,-1763.78 cw(c2443.78,-1763.78) CN3.35@2398.68,-1718.68 ; CN3.35@2361.32,-1681.32 ccw(c2316.22,-1636.22) 2380,-1636.22 ccw(c2443.78,-1636.22) CN3.35@2398.68,-1681.32 ; CN3.33@2361.32,-1618.68 cw(c2316.22,-1663.78) 2380,-1663.78 cw(c2443.78,-1663.78) CN3.33@2398.68,-1618.68 ; CN3.33@2380,-1600 CN3.35@2380,-1700 CN3.37@2380,-1800 CN3.39@2380,-1900 CN3.41@2380,-2000 CN3.43@2380,-2100 CN3.45@2380,-2200 2285,-2295 1499.84,-2295 v2(1454.42,-2249.58) 1361.58,-2249.58 1312,-2200 CN1.46@100,-2200 ; CN1.46@100,-2200 CN1.44@100,-2100 CN1.42@100,-2000 CN1.40@100,-1900 CN1.38@100,-1800 CN1.36@100,-1700 CN1.34@100,-1600 112,-1600 774,-938
  other v1: 442,-2270.49 513,-2270.49 591,-2270.49 664,-2270.49 735,-2270.49 823,-2270.49 894,-2270.49 972,-2270.49 1045,-2270.49 1116,-2270.49 1197,-2270.49 -113,-2244 2042,-2238.49 2107,-2238.49 2188,-2238.49 442,-2233.49 513,-2233.49 591,-2233.49 664,-2233.49 735,-2233.49 823,-2233.49 894,-2233.49 972,-2233.49 1045,-2233.49 1116,-2233.49 1197,-2233.49 2637,-2228 2188,-2173.49 2042,-2167.49 2107,-2167.49 1362,-2153.49 1210,-2147.49 1281,-2147.49 2188,-2108.49 1013.59,-2103.49 2042,-2100.49 2107,-2100.49 288,-2099.49 367,-2099.49 465,-2099.49 544,-2099.49 635,-2099.49 714,-2099.49 830.59,-2099.49 909.59,-2099.49 1362,-2082.49 -113,-2078 1210,-2076.49 1281,-2076.49 2637,-2050 2042,-2029.49 2107,-2029.49 1013.59,-2005.49 288,-2001.49 367,-2001.49 465,-2001.49 544,-2001.49 635,-2001.49 714,-2001.49 830.59,-2001.49 909.59,-2001.49 -113,-1972 2637,-1944 1896,-1935.49 1967,-1935.49 2042,-1935.49 1013.59,-1907.49 288,-1903.49 367,-1903.49 465,-1903.49 544,-1903.49 635,-1903.49 714,-1903.49 830.59,-1903.49 909.59,-1903.49 1745,-1864.49 1816,-1864.49 1896,-1864.49 1967,-1864.49 -113,-1863 2637,-1835 288,-1798.49 367,-1798.49 1745,-1793.49 1816,-1793.49 -113,-1760 2637,-1732 288,-1701.49 367,-1701.49 1888,-1669.49 -113,-1662 2637,-1634 1928,-1621.49 288,-1597.49 367,-1597.49 1966,-1559.49 -113,-1558 1617,-1541 2637,-1530 288,-1501.49 367,-1501.49 2011,-1478.49 -113,-1451 507,-1436 2041,-1430.49 2637,-1423 731,-1390 2075,-1387.49 507,-1377 2187,-1357.49 -113,-1351 731,-1331 2637,-1323 288,-1314.49 2213,-1292.49 1568,-1253.49 1639,-1253.49 1717,-1253.49 1790,-1253.49 1861,-1253.49 1949,-1253.49 2020,-1253.49 2098,-1253.49 -113,-1244 1020,-1228 2637,-1216 1567,-1204.49 1638,-1204.49 1716,-1204.49 1789,-1204.49 1860,-1204.49 1948,-1204.49 2019,-1204.49 2097,-1204.49 288,-1203.49 2248,-1197.49 -113,-1151 2637,-1123 288,-1101.49 2154,-1092 -113,-1049 2104,-1028 2637,-1021 950,-1013 288,-1009.49 -113,-952 288,-925.49 2637,-924 849,-899 919,-899 990,-899 1158,-893 2170,-873 2055.62,-867.38 1949,-866 1846,-862 1755,-858 1666,-856 -113,-853 849,-840 919,-840 990,-840 2637,-825 237,-818.49 849,-768 919,-768 990,-768 2177,-763 2277,-763 2062,-761 -113,-750 1960,-750 2637,-722 1603,-711 1674,-711 1907,-710 -113,-664 1866,-655 288,-653.49 1603,-652 1674,-652 2637,-636 1560,-628 -113,-560 2637,-532 288,-503.49 1370,-477 -113,-455 2179,-439 1498,-429 1568,-429 1639,-429 2637,-427 1498,-370 1568,-370 1639,-370 -113,-350 2174,-346 2637,-322 1498,-298 1568,-298 1639,-298 612,-271 682,-271 -113,-260 2170,-253 1826,-252 1897,-252 288,-239.49 1498,-239 1568,-239 1639,-239 2637,-232 612,-212 682,-212 1348,-201 1826,-193 1897,-193 -113,-159 1498,-158 847,-140 945,-140 1015,-140 1086,-140 2637,-131 288,-125.49 2105,-124 1498,-99 379,-92 449,-92 2105,-65 2176,-65 1310,-52 1381,-52 840,-46 938,-46 1008,-46 1079,-46 379,-33 449,-33 2105,-6 2176,-6 -101,-3 1490,6 1381,7 668,51 738,51 809,51 907,51 977,51 1048,51 1169,51 1239,51 1310,51 2105,53 2176,53 -101,60 -3,60 1569,91 668,110 738,110 809,110 907,110 977,110 1048,110 1169,110 1239,110 1310,110 -101,119 -3,119 67,119 138,119 259,119 329,119 400,119 -62,225.61 2062,227.58 2135,227.58 2245.69,227.58 2318.69,227.58 2415.69,227.58 2488.69,227.58 2612,227.58 -113,228.61 1670,245.58 1821,245.58 2062,310.58 2135,310.58 2245.69,310.58 2318.69,310.58 2415.69,310.58 2488.69,310.58 2612,310.58 -62,313.61 -113,316.61 645,336 715,336 786,336 1755,365 1821,365 -62,383.61 -113,386.61 413,397 2040,396.58 2113,396.58 642,404 712,404 783,404 2612,414 1755,448 1821,448 410,465 -62,474 -113,477 2613,515 2094,524 2167,524 -62,562 -113,565 2613,586 421,624 491,624 562,624 871,624 941,624 1012,624 -62,632 -113,635 2613,669 418,692 488,692 559,692 868,692 938,692 1009,692 -62,703 -113,706 2446,746 2517,746 1623,749 1703,749 1774,749 1852,749 1925,749 1996,749 2083,749 2156,749 2227,749 2312,749 2376,749 -62,793 -113,796 2376,817 2446,817 2517,817 1552,820 1623,820 1703,820 1774,820 1852,820 1925,820 1996,820 2083,820 2156,820 2227,820 2312,820 209,858 299,858 394,858 464,858 535,858 623,858 -62,888 -113,891 2312,900 2376,900 2446,900 2517,900 1482,903 1552,903 1623,903 1703,903 1774,903 1852,903 1925,903 1996,903 2083,903 2156,903 2227,903 206,926 296,926 391,926 461,926 532,926 620,926 1703,1008 1774,1008 1852,1008 1925,1008 1996,1008 2083,1008 2156,1008 2227,1008 -41,1062 47,1062 117,1062 188,1062 278,1062 373,1062 443,1062 514,1062 602,1062 672,1062 743,1062 833,1062 903,1062 974,1062 1132,1062 1203,1062 1267,1062 1337,1062 1482,1062 1552,1062 1623,1062 1703,1062 1774,1062 1852,1062 1925,1062 1996,1062 2083,1062 2156,1062 2227,1062 2312,1062 2376,1062 2446,1062 2517,1062 -42,1117 46,1117 116,1117 187,1117 277,1117 372,1117 442,1117 513,1117 601,1117 671,1117 742,1117 832,1117 902,1117 973,1117 1061,1117 1131,1117 1202,1117 1266,1117 1336,1117 1407,1117 1482,1117 1552,1117 1623,1117 1703,1117 1774,1117 1852,1117 1925,1117 1996,1117 2083,1117 2156,1117 2227,1117 2312,1117 2376,1117 2446,1117 2517,1117
NetC11_2: C11.2 U3.4 | length 430.1
  Top Layer w10: C11.2@782.1,546 785.1,543 U3.4@1137,543 ; C11.2@790.93,537.16 cw(c805.03,523.06) 805.03,543 ; C11.2@790.93,554.84 ccw(c819.52,583.42) 819.52,543 ; U3.4@1104.05,538.05 ccw(c1092.1,526.1) 1092.1,543 ccw(c1092.1,559.9) U3.4@1104.05,547.95
NetD1_1: D1.1 R1.2 | length 170.3
  Top Layer w10: R1.2@772.26,706.82 cw(c750.92,685.49) 781.1,685.49 cw(c811.27,685.49) R1.2@789.93,706.82 ; D1.1@774.02,637.73 ccw(c756.95,654.8) 781.1,654.8 ccw(c805.24,654.8) D1.1@788.17,637.73 ; D1.1@781.1,630.66 R1.2@781.1,715.66
NetD2_1: D2.1 R2.1 | length 417.7
  Top Layer w10: v1@1139.18,-216.18 ccw(c1127.56,-204.56) 1144,-204.56 ccw(c1160.44,-204.56) v1@1148.82,-216.18 ; v1(1144,-221) 1144,-163 D2.1@1223,-84 ; D2.1@1213,-84 cw(c1188.86,-84) 1205.93,-101.07 cw(c1223,-118.14) D2.1@1223,-94
  Bottom Layer w10: R2.1@1135.16,-323.16 ccw(c1113.82,-301.82) 1144,-301.82 ccw(c1174.18,-301.82) R2.1@1152.84,-323.16 ; v1@1139.18,-225.82 cw(c1127.56,-237.44) 1144,-237.44 cw(c1160.44,-237.44) v1@1148.82,-225.82 ; R2.1@1144,-332 v1(1144,-221)
NetD5_2: D5.2 R5.2 | length 236
  Top Layer w10: D5.2@1887.98,-2241.04 cw(c1887.98,-2265.18) 1905.05,-2248.11 cw(c1922.12,-2231.04) D5.2@1897.98,-2231.04 ; D5.2@1887.98,-2231.04 v1(1922.98,-2266.04) ; v1@1916.17,-2266.04 ccw(c1899.73,-2266.04) 1911.35,-2254.41 ccw(c1922.98,-2242.79) v1@1922.98,-2259.23
  Bottom Layer w10: R5.2@1887.98,-2243.54 cw(c1887.98,-2273.72) 1909.32,-2252.38 cw(c1930.66,-2231.04) R5.2@1900.48,-2231.04 ; R5.2@1887.98,-2231.04 v1(1922.98,-2266.04) ; v1@1916.17,-2266.04 ccw(c1899.73,-2266.04) 1911.35,-2254.41 ccw(c1922.98,-2242.79) v1@1922.98,-2259.23
NetD6_2: D6.2 R6.1 | length 236
  Top Layer w10: D6.2@1887.98,-2125 cw(c1887.98,-2149.14) 1905.05,-2132.07 cw(c1922.12,-2115) D6.2@1897.98,-2115 ; D6.2@1887.98,-2115 v1(1922.98,-2150) ; v1@1916.17,-2150 ccw(c1899.73,-2150) 1911.35,-2138.37 ccw(c1922.98,-2126.75) v1@1922.98,-2143.19
  Bottom Layer w10: R6.1@1887.98,-2127.5 cw(c1887.98,-2157.68) 1909.32,-2136.34 cw(c1930.66,-2115) R6.1@1900.48,-2115 ; R6.1@1887.98,-2115 v1(1922.98,-2150) ; v1@1916.17,-2150 ccw(c1899.73,-2150) 1911.35,-2138.37 ccw(c1922.98,-2126.75) v1@1922.98,-2143.19
NetD7_2: D7.2 R7.1 | length 236
  Top Layer w10: D7.2@1887.98,-2005.99 cw(c1887.98,-2030.13) 1905.05,-2013.06 cw(c1922.12,-1995.99) D7.2@1897.98,-1995.99 ; D7.2@1887.98,-1995.99 v1(1922.98,-2030.99) ; v1@1916.17,-2030.99 ccw(c1899.73,-2030.99) 1911.35,-2019.36 ccw(c1922.98,-2007.74) v1@1922.98,-2024.18
  Bottom Layer w10: R7.1@1887.98,-2008.49 cw(c1887.98,-2038.67) 1909.32,-2017.33 cw(c1930.66,-1995.99) R7.1@1900.48,-1995.99 ; R7.1@1887.98,-1995.99 v1(1922.98,-2030.99) ; v1@1916.17,-2030.99 ccw(c1899.73,-2030.99) 1911.35,-2019.36 ccw(c1922.98,-2007.74) v1@1922.98,-2024.18
NetD8_1: D8.1 R8.2 | length 231.9
  Top Layer w10: v1(1506,452) 1538,484 D8.1@1538,490 ; v1@1506,458.81 ccw(c1506,475.25) 1517.63,463.63 ccw(c1529.25,452) v1@1512.81,452 ; 1516.69,462.69 ccw(c1489.37,490) D8.1@1528,490
  Bottom Layer w10: v1(1506,452) R8.2@1538,484 ; v1@1506,458.81 ccw(c1506,475.25) 1517.63,463.63 ccw(c1529.25,452) v1@1512.81,452 ; v1@1512.42,458.42 ccw(c1480.84,490) R8.2@1525.5,490 ; R8.2@1526.9,472.9 cw(c1538,461.81) R8.2@1538,477.5
  Bottom Layer w20: R8.2@1538,484 R8.2@1538,490
NetD9_1: D9.1 R9.2 | length 219
  Top Layer w10: v1(1509,376) D9.1@1538,405 ; v1@1509,382.81 ccw(c1509,399.25) 1520.63,387.63 ccw(c1532.26,376) v1@1515.81,376 ; D9.1@1528,405 cw(c1503.86,405) 1520.93,387.93 cw(c1538,370.86) D9.1@1538,395
  Bottom Layer w10: v1(1509,376) R9.2@1538,405 ; v1@1509,382.81 ccw(c1509,399.25) 1520.63,387.63 ccw(c1532.25,376) v1@1515.81,376 ; R9.2@1525.5,405 cw(c1495.32,405) 1516.66,383.66 cw(c1538,362.32) R9.2@1538,392.5
NetJP4_1: JP4.1 R5.1 | length 381.1
  Bottom Layer w10: JP4.1@1715,-2226 1822.94,-2226 R5.1@1827.98,-2231.04 ; JP4.1@1730.14,-2241.14 cw(c1766.71,-2277.71) 1766.71,-2226 cw(c1766.71,-2174.29) JP4.1@1730.14,-2210.86 ; JP4.1@1737.22,-2248.22 cw(c1790.85,-2301.85) 1790.85,-2226 cw(c1790.85,-2150.15) JP4.1@1737.22,-2203.78 ; 1785.64,-2226 cw(c1785.64,-2273.38) R5.1@1819.14,-2239.88 ; 1809.78,-2226 cw(c1809.78,-2249.24) R5.1@1826.21,-2232.81 ; 1809.97,-2226 ccw(c1809.97,-2213.03) R5.1@1819.14,-2222.2
NetJP5_1: JP5.1 R6.2 | length 376.4
  Bottom Layer w10: JP5.1@1715,-2109 1821.98,-2109 R6.2@1827.98,-2115 ; JP5.1@1730.14,-2124.14 cw(c1766.71,-2160.71) 1766.71,-2109 cw(c1766.71,-2057.29) JP5.1@1730.14,-2093.86 ; JP5.1@1737.22,-2131.22 cw(c1790.85,-2184.85) 1790.85,-2109 cw(c1790.85,-2033.15) JP5.1@1737.22,-2086.78 ; 1783.32,-2109 cw(c1783.32,-2159.66) R6.2@1819.14,-2123.84 ; 1807.46,-2109 cw(c1807.46,-2135.52) R6.2@1826.21,-2116.77
NetJP6_1: JP6.1 R7.2 | length 394.7
  Bottom Layer w10: JP6.1@1715,-1992 1718.99,-1995.99 R7.2@1827.98,-1995.99 ; JP6.1@1723.07,-1983.93 ccw(c1752.2,-1954.8) 1752.2,-1995.99 ; JP6.1@1730.14,-2007.14 cw(c1757.07,-2034.07) 1757.07,-1995.99 ; JP6.1@1730.14,-1976.86 ccw(c1776.34,-1930.66) 1776.34,-1995.99 ; JP6.1@1737.22,-2014.22 cw(c1781.22,-2058.22) 1781.22,-1995.99 ; JP6.1@1737.22,-1969.78 ccw(c1800.48,-1906.52) 1800.48,-1995.99 ; R7.2@1819.14,-2004.83 ccw(c1797.8,-2026.17) 1797.8,-1995.99 ccw(c1797.8,-1965.81) R7.2@1819.14,-1987.15
PA0: CN1.17 U2.10 | length 1672.3
  Top Layer w10: CN1.17@0,-800 51,-851 ; CN1.17@0.78,-821.4 cw(c2.43,-867.1) 34.76,-834.76 cw(c67.1,-802.43) CN1.17@21.4,-800.78 ; CN1.17@1.14,-831.4 cw(c3.57,-898.42) 51,-851 ; CN1.17@31.4,-801.14 ccw(c98.42,-803.57) 51,-851 ; U2.10@1054.83,-1458.9 994.1,-1458.9 913,-1540 778,-1540 689,-1451 689,-1294 246,-851 51,-851
PA1: CN1.19 U2.11 | length 1675.6
  Top Layer w10: CN1.19@0,-900 50,-950 ; CN1.19@1.09,-921.39 cw(c3.3,-964.87) 34.08,-934.08 cw(c64.87,-903.3) CN1.19@21.39,-901.09 ; CN1.19@1.6,-931.38 cw(c4.84,-995.15) 50,-950 ; CN1.19@31.38,-901.6 ccw(c95.15,-904.84) 50,-950 ; 1001.13,-1487.87 cw(c1021.37,-1508.12) U2.11@1021.37,-1479.49 ; 1005.52,-1483.48 cw(c1016.73,-1494.68) U2.11@1021.12,-1479.45 ; U2.11@1054.83,-1478.58 1054.25,-1478 1011,-1478 915,-1574 759,-1574 644,-1459 644,-1318 276,-950 50,-950
PA2: CN1.21 U2.12 | length 1627.1
  Top Layer w10: CN1.21@0,-1000 51,-1051 ; CN1.21@0.78,-1021.4 cw(c2.43,-1067.1) 34.76,-1034.76 cw(c67.1,-1002.43) CN1.21@21.4,-1000.78 ; CN1.21@1.14,-1031.4 cw(c3.57,-1098.42) 51,-1051 ; CN1.21@31.4,-1001.14 ccw(c98.42,-1003.57) 51,-1051 ; U2.12@1054.83,-1498.27 1054.83,-1556.17 1010,-1601 740,-1601 601,-1462 601,-1357 295,-1051 51,-1051
PA3: CN1.23 U2.13 | length 1609.6
  Top Layer w10: CN1.23@0,-1100 50,-1150 ; CN1.23@1.09,-1121.39 cw(c3.3,-1164.87) 34.08,-1134.08 cw(c64.87,-1103.3) CN1.23@21.39,-1101.09 ; CN1.23@1.6,-1131.38 cw(c4.84,-1195.15) 50,-1150 ; CN1.23@31.38,-1101.6 ccw(c95.15,-1104.84) 50,-1150 ; U2.13@1123.73,-1567.17 1099.83,-1567.17 1033,-1634 714,-1634 569,-1489 569,-1391 328,-1150 50,-1150
PA4: CN1.25 U2.14 | length 1601.6
  Top Layer w10: CN1.25@0,-1200 51,-1251 ; CN1.25@0.78,-1221.4 cw(c2.43,-1267.1) 34.76,-1234.76 cw(c67.1,-1202.43) CN1.25@21.4,-1200.78 ; CN1.25@1.14,-1231.4 cw(c3.57,-1298.42) 51,-1251 ; CN1.25@31.4,-1201.14 ccw(c98.42,-1203.57) 51,-1251 ; U2.14@1143.42,-1567.17 1143,-1567.58 1143,-1634 1111,-1666 696,-1666 281,-1251 51,-1251
PA5: CN1.27 U2.15 | length 1603.1
  Top Layer w10: CN1.27@0,-1300 49,-1349 ; CN1.27@1.41,-1321.37 cw(c4.14,-1362.66) 33.4,-1333.4 cw(c62.66,-1304.14) CN1.27@21.37,-1301.41 ; CN1.27@2.07,-1331.35 cw(c6.07,-1391.92) 49,-1349 ; CN1.27@31.35,-1302.07 ccw(c91.92,-1306.07) 49,-1349 ; U2.15@1163.1,-1567.17 1163.1,-1651.9 1120,-1695 669,-1695 323,-1349 49,-1349
PA6: CN1.29 U2.16 | length 1624
  Top Layer w10: CN1.29@0,-1400 51,-1451 ; CN1.29@0.78,-1421.4 cw(c2.43,-1467.1) 34.76,-1434.76 cw(c67.1,-1402.43) CN1.29@21.4,-1400.78 ; CN1.29@1.14,-1431.4 cw(c3.57,-1498.42) 51,-1451 ; CN1.29@31.4,-1401.14 ccw(c98.42,-1403.57) 51,-1451 ; U2.16@1182.79,-1567.17 1182.79,-1668.21 1130,-1721 641,-1721 371,-1451 51,-1451
PA7: CN1.31 U2.17 | length 1624.7
  Top Layer w10: CN1.31@0,-1500 49,-1549 ; CN1.31@1.41,-1521.37 cw(c4.14,-1562.66) 33.4,-1533.4 cw(c62.66,-1504.14) CN1.31@21.37,-1501.41 ; CN1.31@2.07,-1531.35 cw(c6.07,-1591.92) 49,-1549 ; CN1.31@31.35,-1502.07 ccw(c91.92,-1506.07) 49,-1549 ; U2.17@1202.47,-1567.17 1202.47,-1686.53 1140,-1749 614,-1749 414,-1549 49,-1549
PA8: CN3.38 U2.29 | length 1449.5
  Top Layer w10: U2.29@1409.17,-1419.53 1886.53,-1419.53 2317,-1850 2430,-1850 ; CN3.38@2448.62,-1801.6 cw(c2384.85,-1804.84) 2430,-1850 ; CN3.38@2458.61,-1801.09 cw(c2415.13,-1803.3) 2445.92,-1834.08 cw(c2476.7,-1864.87) CN3.38@2478.91,-1821.39 ; CN3.38@2478.4,-1831.38 ccw(c2475.16,-1895.15) 2430,-1850 ; CN3.38@2480,-1800 2430,-1850
PA9: CN3.36 U2.30 | length 1422.8
  Top Layer w10: U2.30@1409.17,-1399.84 1975.84,-1399.84 2327,-1751 2429,-1751 ; CN3.36@2448.6,-1701.14 cw(c2381.58,-1703.57) 2429,-1751 ; CN3.36@2458.6,-1700.78 cw(c2412.9,-1702.43) 2445.24,-1734.76 cw(c2477.57,-1767.1) CN3.36@2479.22,-1721.4 ; CN3.36@2478.86,-1731.4 ccw(c2476.43,-1798.42) 2429,-1751 ; CN3.36@2480,-1700 2429,-1751
PA10: CN3.34 U2.31 | length 1382.9
  Top Layer w10: U2.31@1409.17,-1380.16 2034.16,-1380.16 2304,-1650 2430,-1650 ; CN3.34@2448.62,-1601.6 cw(c2384.85,-1604.84) 2430,-1650 ; CN3.34@2458.61,-1601.09 cw(c2415.13,-1603.3) 2445.92,-1634.08 cw(c2476.7,-1664.87) CN3.34@2478.91,-1621.39 ; CN3.34@2478.4,-1631.38 ccw(c2475.16,-1695.15) 2430,-1650 ; CN3.34@2480,-1600 2430,-1650
PA11: CN3.32 U2.32 | length 1356.2
  Top Layer w10: U2.32@1409.17,-1360.47 2085.47,-1360.47 2276,-1551 2429,-1551 ; CN3.32@2448.6,-1501.14 cw(c2381.58,-1503.57) 2429,-1551 ; CN3.32@2458.6,-1500.78 cw(c2412.9,-1502.43) 2445.24,-1534.76 cw(c2477.57,-1567.1) CN3.32@2479.22,-1521.4 ; CN3.32@2478.86,-1531.4 ccw(c2476.43,-1598.42) 2429,-1551 ; CN3.32@2480,-1500 2429,-1551
PA12: CN3.30 U2.33 | length 1323
  Top Layer w10: U2.33@1409.17,-1340.79 2120.79,-1340.79 2231,-1451 2429,-1451 ; CN3.30@2448.6,-1401.14 cw(c2381.58,-1403.57) 2429,-1451 ; CN3.30@2458.6,-1400.78 cw(c2412.9,-1402.43) 2445.24,-1434.76 cw(c2477.57,-1467.1) CN3.30@2479.22,-1421.4 ; CN3.30@2478.86,-1431.4 ccw(c2476.43,-1498.42) 2429,-1451 ; CN3.30@2480,-1400 2429,-1451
